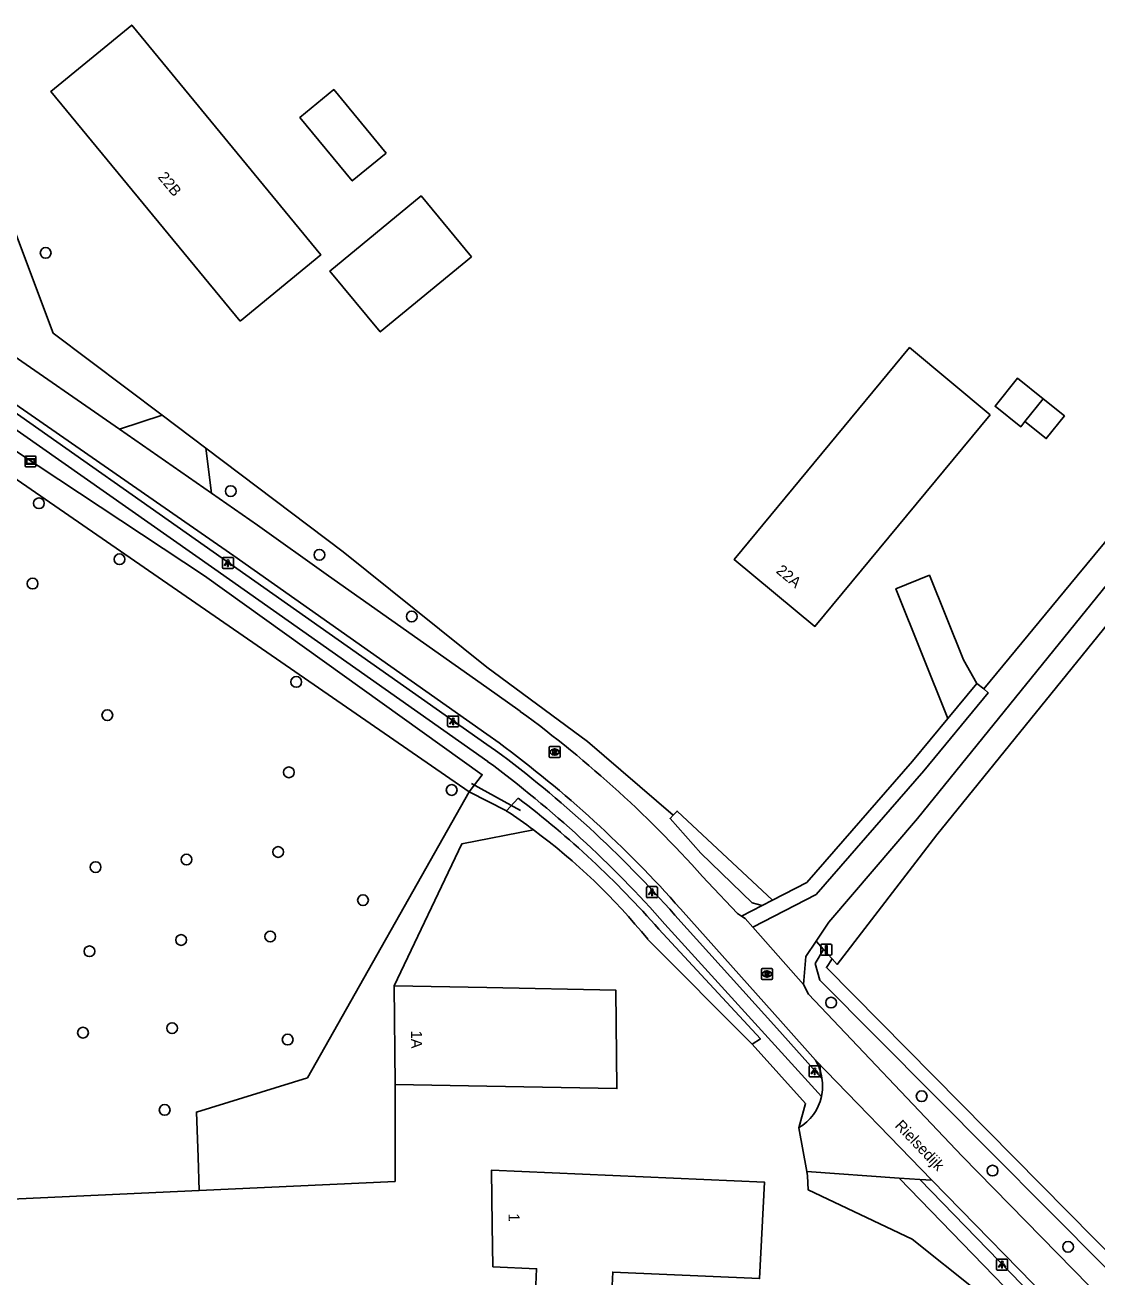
# Model space of a CAD drawing. Extents: x 163863 to 164644, y 379566 to 382155.
# Drawn here: x 164457.9 to 164555.6, y 381598.9 to 381713 of the extents above; entities that cross this region are included whole.
import ezdxf

# ---------------------------------------------------------------- set-up
doc = ezdxf.new("R2010")
doc.units = 0
for name, color, linetype in [('IMGEO_Boom', 7, 'Continuous'), ('IMGEO_Duiker', 7, 'Continuous'), ('IMGEO_Fietspad_open', 7, 'Continuous'), ('IMGEO_Groenvoorziening', 7, 'Continuous'), ('IMGEO_Lichtpunt', 7, 'Continuous'), ('IMGEO_Loofbos', 7, 'Continuous'), ('IMGEO_Openbare_ruimte_label', 7, 'Continuous'), ('IMGEO_Pand', 7, 'Continuous'), ('IMGEO_Pand_nummerreeks', 7, 'Continuous'), ('IMGEO_Rijbaan_lokaal_gesloten', 7, 'Continuous'), ('IMGEO_Rijbaan_lokaal_halfverhard', 7, 'Continuous'), ('IMGEO_Rioolput', 7, 'Continuous'), ('IMGEO_Verkeersbordpaal', 7, 'Continuous'), ('IMGEO_Verklikker', 7, 'Continuous'), ('IMGEO_Voetpad_open', 7, 'Continuous'), ('IMGEO_Waterloop', 7, 'Continuous')]:
    doc.layers.add(name, color=color, linetype=linetype)

msp = doc.modelspace()

# ---------------------------------------------------------------- linework, layer by layer
at = {"layer": 'IMGEO_Boom'}
for centre in [(164459.81, 381692.21), (164476.67, 381670.5), (164459.2, 381669.39), (164484.75, 381664.69), (164466.54, 381664.29), (164458.62, 381662.07), (164493.16, 381659.07), (164482.64, 381653.11), (164465.43, 381650.08), (164481.97, 381644.87), (164496.8, 381643.26), (164480.99, 381637.61), (164464.36, 381636.23), (164472.64, 381636.92), (164488.72, 381633.22), (164472.15, 381629.59), (164480.27, 381629.91), (164463.8, 381628.56), (164531.36, 381623.88), (164471.33, 381621.55), (164463.21, 381621.14), (164481.86, 381620.51), (164539.61, 381615.35), (164470.65, 381614.1), (164546.07, 381608.57), (164552.95, 381601.62)]:
    msp.add_circle(centre, 0.489, dxfattribs=at)
at = {"layer": 'IMGEO_Duiker'}
msp.add_lwpolyline([(164503.07, 381641.38), (164498.6, 381643.85)], dxfattribs=at)
at = {"layer": 'IMGEO_Fietspad_open'}
for points in [[(164537.57, 381607.88), (164547.15, 381597.97)], [(164537.57, 381607.88), (164539.43, 381607.77)], [(164555.48, 381592.17), (164555.02, 381591.73), (164551.82, 381595.01), (164539.43, 381607.77)]]:
    msp.add_lwpolyline(points, dxfattribs=at)
at = {"layer": 'IMGEO_Groenvoorziening'}
for points in [[(164452.84, 381705.1), (164456.24, 381696.23), (164460.51, 381684.89), (164470.41, 381677.43)], [(164590.11, 381705.69), (164584.68, 381698), (164585.57, 381697.39), (164584.37, 381695.76), (164568.78, 381674.53), (164569.41, 381674.27), (164540.99, 381639.17), (164531.9, 381627.37), (164531.45, 381627.87)], [(164474.4, 381674.42), (164486.92, 381664.98), (164500, 381654.46), (164509.16, 381647.67), (164516.98, 381640.96)], [(164530.68, 381628.73), (164530, 381629.48)], [(164528.41, 381612.47), (164529.03, 381614.69), (164524.17, 381620.08)], [(164546.1, 381596.15), (164544.61, 381597.64), (164538.75, 381602.33), (164529.28, 381606.81), (164529.21, 381608.09), (164529.15, 381608.49)], [(164473.79, 381606.76), (164452.07, 381605.75)]]:
    msp.add_lwpolyline(points, dxfattribs=at)
at = {"layer": 'IMGEO_Lichtpunt'}
for p, q in [((164475.92, 381664.35), (164475.92, 381663.54)), ((164475.92, 381664.35), (164475.92, 381663.54)), ((164476.82, 381664.44), (164476.01, 381664.44)), ((164476.82, 381664.44), (164476.01, 381664.44)), ((164476.91, 381663.54), (164476.91, 381664.35)), ((164476.91, 381663.54), (164476.91, 381664.35)), ((164476.01, 381663.45), (164476.82, 381663.45)), ((164476.01, 381663.45), (164476.82, 381663.45)), ((164496.43, 381649.91), (164496.43, 381649.1)), ((164496.43, 381649.91), (164496.43, 381649.1)), ((164497.34, 381650), (164496.53, 381650)), ((164497.34, 381650), (164496.53, 381650)), ((164497.43, 381649.1), (164497.43, 381649.91)), ((164497.43, 381649.1), (164497.43, 381649.91)), ((164496.53, 381649.01), (164497.34, 381649.01)), ((164496.53, 381649.01), (164497.34, 381649.01)), ((164514.55, 381634.35), (164514.55, 381633.54)), ((164514.55, 381634.35), (164514.55, 381633.54)), ((164515.45, 381634.45), (164514.65, 381634.45)), ((164515.45, 381634.45), (164514.65, 381634.45)), ((164515.55, 381633.54), (164515.55, 381634.35)), ((164515.55, 381633.54), (164515.55, 381634.35)), ((164514.65, 381633.45), (164515.45, 381633.45)), ((164514.65, 381633.45), (164515.45, 381633.45)), ((164529.37, 381618.03), (164529.37, 381617.22)), ((164529.37, 381618.03), (164529.37, 381617.22)), ((164530.27, 381618.12), (164529.46, 381618.12)), ((164530.27, 381618.12), (164529.46, 381618.12)), ((164529.46, 381617.12), (164530.27, 381617.12)), ((164529.46, 381617.12), (164530.27, 381617.12)), ((164530.36, 381617.22), (164530.36, 381618.03)), ((164530.36, 381617.22), (164530.36, 381618.03)), ((164546.44, 381600.41), (164546.44, 381599.6)), ((164546.44, 381600.41), (164546.44, 381599.6)), ((164547.34, 381600.5), (164546.53, 381600.5)), ((164547.34, 381600.5), (164546.53, 381600.5)), ((164547.43, 381599.6), (164547.43, 381600.41)), ((164547.43, 381599.6), (164547.43, 381600.41)), ((164546.53, 381599.51), (164547.34, 381599.51)), ((164546.53, 381599.51), (164547.34, 381599.51))]:
    msp.add_line(p, q, dxfattribs=at)
for points in [[(164476.29, 381664.01), (164476.33, 381663.99), (164476.14, 381663.72), (164476.1, 381663.75), (164476.29, 381664.01)], [(164476.39, 381663.97), (164476.44, 381663.97), (164476.44, 381663.64), (164476.39, 381663.64), (164476.39, 381663.97)], [(164476.5, 381663.99), (164476.54, 381664.01), (164476.73, 381663.75), (164476.69, 381663.72), (164476.5, 381663.99)], [(164496.81, 381649.57), (164496.85, 381649.54), (164496.66, 381649.28), (164496.62, 381649.31), (164496.81, 381649.57)], [(164496.91, 381649.52), (164496.96, 381649.52), (164496.96, 381649.2), (164496.91, 381649.2), (164496.91, 381649.52)], [(164497.02, 381649.54), (164497.06, 381649.57), (164497.24, 381649.31), (164497.21, 381649.28), (164497.02, 381649.54)], [(164514.93, 381634.01), (164514.97, 381633.99), (164514.78, 381633.72), (164514.74, 381633.75), (164514.93, 381634.01)], [(164515.03, 381633.97), (164515.08, 381633.97), (164515.08, 381633.64), (164515.03, 381633.64), (164515.03, 381633.97)], [(164515.14, 381633.99), (164515.18, 381634.01), (164515.36, 381633.75), (164515.33, 381633.72), (164515.14, 381633.99)], [(164529.74, 381617.69), (164529.78, 381617.66), (164529.59, 381617.4), (164529.55, 381617.43), (164529.74, 381617.69)], [(164529.84, 381617.64), (164529.89, 381617.64), (164529.89, 381617.32), (164529.84, 381617.32), (164529.84, 381617.64)], [(164529.95, 381617.66), (164529.99, 381617.69), (164530.18, 381617.43), (164530.14, 381617.4), (164529.95, 381617.66)], [(164546.81, 381600.07), (164546.85, 381600.04), (164546.66, 381599.78), (164546.62, 381599.81), (164546.81, 381600.07)], [(164546.91, 381600.02), (164546.96, 381600.02), (164546.96, 381599.7), (164546.91, 381599.7), (164546.91, 381600.02)], [(164547.02, 381600.04), (164547.06, 381600.07), (164547.25, 381599.81), (164547.21, 381599.78), (164547.02, 381600.04)]]:
    msp.add_lwpolyline(points, dxfattribs=at)
for centre in [(164476.42, 381664.15), (164496.93, 381649.71), (164515.05, 381634.15), (164529.87, 381617.82), (164546.94, 381600.21)]:
    msp.add_circle(centre, 0.0994, dxfattribs=at)
for centre, start, end in [((164476.01, 381664.35), 90, 180), ((164476.01, 381664.35), 90, 180), ((164476.82, 381664.35), 0, 90), ((164476.82, 381664.35), 0, 90), ((164476.01, 381663.54), 180, 270), ((164476.01, 381663.54), 180, 270), ((164476.82, 381663.54), 270, 0), ((164476.82, 381663.54), 270, 360), ((164496.53, 381649.91), 90, 180), ((164496.53, 381649.91), 90, 180), ((164496.53, 381649.1), 180, 270), ((164496.53, 381649.1), 180, 270), ((164497.34, 381649.91), 0, 90), ((164497.34, 381649.91), 0, 90), ((164497.34, 381649.1), 270, 0), ((164497.34, 381649.1), 270, 360), ((164514.65, 381634.35), 90, 180), ((164514.65, 381634.35), 90, 180), ((164515.45, 381634.35), 0, 90), ((164515.45, 381634.35), 0, 90), ((164514.65, 381633.54), 180, 270), ((164514.65, 381633.54), 180, 270), ((164515.45, 381633.54), 270, 0), ((164515.45, 381633.54), 270, 360), ((164529.46, 381618.03), 90, 180), ((164529.46, 381618.03), 90, 180), ((164529.46, 381617.22), 180, 270), ((164529.46, 381617.22), 180, 270), ((164530.27, 381618.03), 0, 90), ((164530.27, 381618.03), 0, 90), ((164530.27, 381617.22), 270, 0), ((164530.27, 381617.22), 270, 360), ((164546.53, 381600.41), 90, 180), ((164546.53, 381600.41), 90, 180), ((164547.34, 381600.41), 0, 90), ((164547.34, 381600.41), 0, 90), ((164546.53, 381599.6), 180, 270), ((164546.53, 381599.6), 180, 270), ((164547.34, 381599.6), 270, 0), ((164547.34, 381599.6), 270, 360)]:
    msp.add_arc(centre, 0.0946, start, end, dxfattribs=at)
at = {"layer": 'IMGEO_Loofbos'}
for points in [[(164473.79, 381606.76), (164473.69, 381609.8), (164473.55, 381613.91), (164483.66, 381617.04), (164498.4, 381643.1)], [(164498.4, 381643.1), (164501.8, 381641.35)], [(164504.24, 381639.64), (164497.72, 381638.34), (164491.56, 381625.42)], [(164491.64, 381616.41), (164491.64, 381607.59), (164473.79, 381606.76)]]:
    msp.add_lwpolyline(points, dxfattribs=at)
at = {"layer": 'IMGEO_Pand'}
for points in [[(164477.52, 381685.99), (164460.28, 381706.92), (164467.65, 381712.98), (164484.87, 381692.03), (164477.52, 381685.99)], [(164490.83, 381701.31), (164487.74, 381698.77), (164482.97, 381704.55), (164486.06, 381707.1), (164490.83, 381701.31)], [(164498.59, 381691.86), (164490.29, 381685.01), (164485.71, 381690.56), (164494.01, 381697.41), (164498.59, 381691.86)], [(164545.84, 381677.45), (164529.89, 381658.17), (164522.53, 381664.27), (164538.51, 381683.58), (164545.84, 381677.45)], [(164549.02, 381676.84), (164548.64, 381676.37), (164546.3, 381678.24), (164548.33, 381680.78), (164550.67, 381678.91)], [(164550.67, 381678.91), (164549.02, 381676.84)], [(164550.67, 381678.91), (164552.61, 381677.35), (164550.96, 381675.29), (164549.02, 381676.84)], [(164491.64, 381616.41), (164491.56, 381625.42)], [(164491.56, 381625.42), (164500, 381625.26), (164511.74, 381625.03), (164511.85, 381616.05), (164500, 381616.26), (164491.64, 381616.41)], [(164511.3, 381595.66), (164504.37, 381595.96), (164504.54, 381599.63), (164500.55, 381599.81), (164500.49, 381603.61), (164500.42, 381608.61), (164525.3, 381607.51), (164524.84, 381598.73), (164511.47, 381599.32), (164511.3, 381595.66)]]:
    msp.add_lwpolyline(points, dxfattribs=at)
at = {"layer": 'IMGEO_Rijbaan_lokaal_gesloten'}
for points in [[(164466.53, 381676.14), (164455.77, 381683.63)], [(164456.32, 381678.95), (164476.96, 381664.61), (164500, 381648.34), (164501.11, 381647.55)], [(164466.53, 381676.14), (164474.91, 381670.3)], [(164474.91, 381670.3), (164479.1, 381667.39), (164485.58, 381662.79), (164500, 381652.59), (164503.05, 381650.43)], [(164520.13, 381634.85), (164522.82, 381632.01), (164523.21, 381631.76)], [(164517.63, 381632.43), (164527, 381621.94), (164529.93, 381618.65)], [(164523.21, 381631.76), (164523.52, 381631.56), (164524.23, 381630.76)], [(164524.23, 381630.76), (164528.86, 381625.54)], [(164568.68, 381588.2), (164567.28, 381587.44), (164566.26, 381587.51), (164564.98, 381587.75), (164543.31, 381609.9), (164529.3, 381624.66), (164528.86, 381625.54)], [(164529.93, 381618.65), (164540.55, 381607.69)], [(164540.55, 381607.69), (164552.4, 381595.54), (164555.45, 381592.38)]]:
    msp.add_lwpolyline(points, dxfattribs=at)
for centre, radius, start, end in [((164440.03, 381564.16), 106.83, 41.429, 53.8516), ((164437.85, 381561.83), 106.54, 41.506, 53.5746)]:
    msp.add_arc(centre, radius, start, end, dxfattribs=at)
at = {"layer": 'IMGEO_Rijbaan_lokaal_halfverhard'}
for points in [[(164545.26, 381652.47), (164553.79, 381662.79), (164565.5, 381676.94), (164583.03, 381701.54)], [(164530, 381629.48), (164531.15, 381631.21), (164539.23, 381640.65), (164567.44, 381675.52), (164585.06, 381700.14)], [(164545.26, 381652.47), (164545.68, 381652.11), (164539.82, 381645.02), (164530, 381633.75), (164524.23, 381630.76)], [(164528.86, 381625.54), (164529.06, 381628.07), (164530, 381629.48)]]:
    msp.add_lwpolyline(points, dxfattribs=at)
at = {"layer": 'IMGEO_Rioolput'}
for p, q in [((164505.67, 381646.29), (164505.67, 381647.15)), ((164505.75, 381647.22), (164506.6, 381647.22)), ((164506.16, 381647), (164506.19, 381647)), ((164506.68, 381647.15), (164506.68, 381646.29)), ((164506.6, 381646.22), (164505.75, 381646.22)), ((164506.18, 381646.44), (164506.16, 381646.44)), ((164525.02, 381626.07), (164525.02, 381626.92)), ((164525.09, 381626.99), (164525.95, 381626.99)), ((164525.51, 381626.77), (164525.53, 381626.77)), ((164526.02, 381626.92), (164526.02, 381626.07)), ((164525.95, 381625.99), (164525.09, 381625.99)), ((164525.53, 381626.21), (164525.5, 381626.21))]:
    msp.add_line(p, q, dxfattribs=at)
for points in [[(164505.67, 381646.29), (164505.67, 381647.15)], [(164505.75, 381647.22), (164506.6, 381647.22)], [(164506.26, 381646.92), (164506.01, 381646.92), (164506.01, 381646.52)], [(164506.19, 381646.84), (164506.14, 381646.84), (164506.14, 381646.76)], [(164506.68, 381647.15), (164506.68, 381646.29)], [(164506.6, 381646.22), (164505.75, 381646.22)], [(164506.01, 381646.52), (164506.14, 381646.52), (164506.14, 381646.68), (164506.15, 381646.68)], [(164506.14, 381646.76), (164506.19, 381646.76)], [(164506.19, 381646.65), (164506.26, 381646.52), (164506.4, 381646.52), (164506.34, 381646.65)], [(164525.02, 381626.07), (164525.02, 381626.92)], [(164525.09, 381626.99), (164525.95, 381626.99)], [(164525.61, 381626.69), (164525.36, 381626.69), (164525.36, 381626.29)], [(164525.36, 381626.29), (164525.48, 381626.29), (164525.48, 381626.46), (164525.49, 381626.46)], [(164525.53, 381626.61), (164525.48, 381626.61), (164525.48, 381626.53)], [(164525.48, 381626.53), (164525.53, 381626.53)], [(164525.54, 381626.43), (164525.61, 381626.29), (164525.75, 381626.29), (164525.68, 381626.42)], [(164526.02, 381626.92), (164526.02, 381626.07)], [(164525.95, 381625.99), (164525.09, 381625.99)]]:
    msp.add_lwpolyline(points, dxfattribs=at)
for centre, radius, start, end in [((164505.75, 381647.14), 0.0765, 91.552, 178.448), ((164505.75, 381647.14), 0.0765, 91.552, 178.448), ((164506.19, 381646.74), 0.0964, 77.0061, 93.1865), ((164506.21, 381646.8), 0.0378, 276.6634, 79.6772), ((164506.26, 381646.81), 0.109, 350.3612, 89.416), ((164506.26, 381646.81), 0.112, 277.5842, 350.9817), ((164506.6, 381647.14), 0.0765, 1.552, 88.448), ((164506.6, 381647.14), 0.0765, 1.552, 88.448), ((164505.75, 381646.3), 0.0765, 181.552, 268.448), ((164505.75, 381646.3), 0.0765, 181.552, 268.448), ((164506.14, 381646.63), 0.0533, 26.0293, 88.6989), ((164506.17, 381646.95), 0.19, 274.7715, 282.9687), ((164506.24, 381646.59), 0.108, 29.5134, 73.7905), ((164506.6, 381646.3), 0.0765, 271.552, 358.448), ((164506.6, 381646.3), 0.0765, 271.552, 358.448), ((164525.1, 381626.92), 0.0765, 91.552, 178.448), ((164525.1, 381626.92), 0.0765, 91.552, 178.448), ((164525.49, 381626.4), 0.0533, 26.0293, 88.6989), ((164525.54, 381626.52), 0.0964, 77.0061, 93.1865), ((164525.52, 381626.72), 0.19, 274.7715, 282.9687), ((164525.55, 381626.57), 0.0378, 276.6634, 79.6772), ((164525.61, 381626.58), 0.109, 350.3612, 89.416), ((164525.61, 381626.58), 0.112, 277.5842, 350.9817), ((164525.59, 381626.37), 0.108, 29.5134, 73.7905), ((164525.94, 381626.92), 0.0765, 1.552, 88.448), ((164525.94, 381626.92), 0.0765, 1.552, 88.448), ((164525.1, 381626.07), 0.0765, 181.552, 268.448), ((164525.1, 381626.07), 0.0765, 181.552, 268.448), ((164525.94, 381626.07), 0.0765, 271.552, 358.448), ((164525.94, 381626.07), 0.0765, 271.552, 358.448)]:
    msp.add_arc(centre, radius, start, end, dxfattribs=at)
for centre, major_axis, ratio, start_param, end_param in [((164506.16, 381646.72), (-0.387, 0.002), 0.722429, 4.712389, 7.853982), ((164506.19, 381646.72), (-0.39, 0.002), 0.717154, 1.570796, 4.712389), ((164525.51, 381626.49), (-0.387, 0.002), 0.722429, 4.712389, 7.853982), ((164525.53, 381626.49), (-0.39, 0.002), 0.717154, 1.570796, 4.712389)]:
    msp.add_ellipse(centre, major_axis=major_axis, ratio=ratio, start_param=start_param, end_param=end_param, dxfattribs=at)
at = {"layer": 'IMGEO_Verkeersbordpaal'}
for p, q in [((164530.43, 381628.3), (164530.43, 381629.1)), ((164530.43, 381629.1), (164530.43, 381628.3)), ((164530.53, 381629.2), (164531.32, 381629.2)), ((164531.32, 381629.2), (164530.53, 381629.2)), ((164531.42, 381629.1), (164531.42, 381628.3)), ((164531.42, 381628.3), (164531.42, 381629.1)), ((164531.32, 381628.2), (164530.53, 381628.2)), ((164530.53, 381628.2), (164531.32, 381628.2))]:
    msp.add_line(p, q, dxfattribs=at)
msp.add_lwpolyline([(164530.85, 381629.08), (164531, 381629.08), (164531, 381628.33), (164530.85, 381628.33), (164530.85, 381629.08)], dxfattribs=at)
for centre, start, end in [((164530.53, 381629.1), 90, 180), ((164530.53, 381629.1), 90, 180), ((164531.32, 381629.1), 0, 90), ((164531.32, 381629.1), 360, 90), ((164530.53, 381628.3), 180, 270), ((164530.53, 381628.3), 180, 270), ((164531.32, 381628.3), 270, 0), ((164531.32, 381628.3), 270, 0)]:
    msp.add_arc(centre, 0.1, start, end, dxfattribs=at)
at = {"layer": 'IMGEO_Verklikker'}
for p, q in [((164457.94, 381672.8), (164457.94, 381673.6)), ((164457.94, 381673.6), (164457.94, 381672.8)), ((164458.04, 381673.7), (164458.83, 381673.7)), ((164458.83, 381673.7), (164458.04, 381673.7)), ((164458.93, 381673.6), (164458.93, 381672.8)), ((164458.93, 381672.8), (164458.93, 381673.6)), ((164458.83, 381672.7), (164458.04, 381672.7)), ((164458.04, 381672.7), (164458.83, 381672.7))]:
    msp.add_line(p, q, dxfattribs=at)
for points in [[(164458.04, 381673.43), (164458.83, 381673.43), (164458.83, 381672.97), (164458.04, 381672.97), (164458.04, 381673.43)], [(164458.11, 381673.37), (164458.11, 381673.03), (164458.77, 381673.03), (164458.77, 381673.37), (164458.11, 381673.37)]]:
    msp.add_lwpolyline(points, dxfattribs=at)
for centre, start, end in [((164458.04, 381673.6), 90, 180), ((164458.04, 381673.6), 90, 180), ((164458.83, 381673.6), 0, 90), ((164458.83, 381673.6), 360, 90), ((164458.04, 381672.8), 180, 270), ((164458.04, 381672.8), 180, 270), ((164458.83, 381672.8), 270, 0), ((164458.83, 381672.8), 270, 0)]:
    msp.add_arc(centre, 0.1, start, end, dxfattribs=at)
at = {"layer": 'IMGEO_Voetpad_open'}
for points in [[(164500.79, 381646.87), (164500, 381647.42), (164475.88, 381664.4), (164455.06, 381679.04)], [(164453.43, 381678.67), (164475.21, 381663.4), (164500.08, 381645.86)], [(164470.41, 381677.43), (164466.53, 381676.14)], [(164470.41, 381677.43), (164474.4, 381674.42)], [(164474.4, 381674.42), (164474.91, 381670.3)], [(164541.99, 381649.77), (164537.26, 381661.6), (164540.32, 381662.83), (164543.41, 381655.11), (164544.64, 381652.97)], [(164541.99, 381649.77), (164544.64, 381652.97)], [(164544.64, 381652.97), (164545.26, 381652.47)], [(164526.03, 381633.22), (164529.15, 381634.83), (164538.79, 381645.9), (164541.99, 381649.77)], [(164525.08, 381632.72), (164526.03, 381633.22)], [(164523.21, 381631.76), (164525.08, 381632.72)], [(164516.23, 381631.03), (164530.48, 381615.32)], [(164530.52, 381616.98), (164526.41, 381621.55), (164517.12, 381631.86)], [(164529.15, 381608.49), (164528.41, 381612.47)], [(164529.15, 381608.49), (164537.57, 381607.88)], [(164539.43, 381607.77), (164540.55, 381607.69)]]:
    msp.add_lwpolyline(points, dxfattribs=at)
for centre, radius, start, end in [((164438.41, 381562.58), 104.86, 41.3558, 53.4947), ((164438.25, 381562.31), 103.94, 41.3936, 53.5014), ((164525.89, 381616.28), 4.69, 8.5904, 30.365), ((164525.91, 381616.28), 4.67, 348.0658, 8.6355), ((164526.31, 381616.18), 4.25, 299.5009, 348.3365)]:
    msp.add_arc(centre, radius, start, end, dxfattribs=at)
at = {"layer": 'IMGEO_Waterloop'}
for points in [[(164498.4, 381643.1), (164499.59, 381644.65), (164474.27, 381662.77), (164453.36, 381676.59), (164452.57, 381675.49), (164452.88, 381674.52)], [(164452.88, 381674.52), (164498.4, 381643.1)], [(164502.86, 381642.51), (164501.8, 381641.35)], [(164516.98, 381640.96), (164517.33, 381641.34), (164526.03, 381633.22)], [(164525.08, 381632.72), (164524.17, 381632.98), (164519.51, 381637.49), (164516.7, 381640.66), (164516.98, 381640.96)], [(164524.17, 381620.08), (164524.93, 381620.58), (164515.67, 381630.58)], [(164524.17, 381620.08), (164514.65, 381629.66)], [(164530.68, 381628.73), (164529.92, 381627.46), (164530.34, 381625.94), (164566.8, 381589.23), (164566.97, 381589.37), (164567.8, 381588.54), (164568.04, 381588.78)], [(164531.45, 381627.87), (164531.06, 381628.3), (164530.68, 381628.73)], [(164531.45, 381627.87), (164530.94, 381627.08), (164567.56, 381589.98), (164567.41, 381589.82), (164568.26, 381588.99), (164568.04, 381588.78)]]:
    msp.add_lwpolyline(points, dxfattribs=at)
for centre, radius, start, end in [((164450.37, 381573.34), 86.83, 41.2377, 52.812), ((164470.8, 381594.55), 56.13, 53.4347, 56.4708), ((164470.2, 381593.71), 57.17, 38.9591, 53.4562)]:
    msp.add_arc(centre, radius, start, end, dxfattribs=at)

# ---------------------------------------------------------------- texts
at = {"layer": 'IMGEO_Openbare_ruimte_label'}
msp.add_text('Rielsedijk', height=1, rotation=313.5416, dxfattribs=at).set_placement((164537.11, 381612.61))
at = {"layer": 'IMGEO_Pand_nummerreeks'}
for s, rotation, p in [('22B', 309.4779, (164469.98, 381699.1)), ('22A', 320.1565, (164526.28, 381663.12)), ('1A', 270.3092, (164493.1, 381621.33)), ('1', 270.6702, (164501.98, 381604.67))]:
    msp.add_text(s, height=1, rotation=rotation, dxfattribs=at).set_placement(p)

doc.saveas('drawing.dxf')
